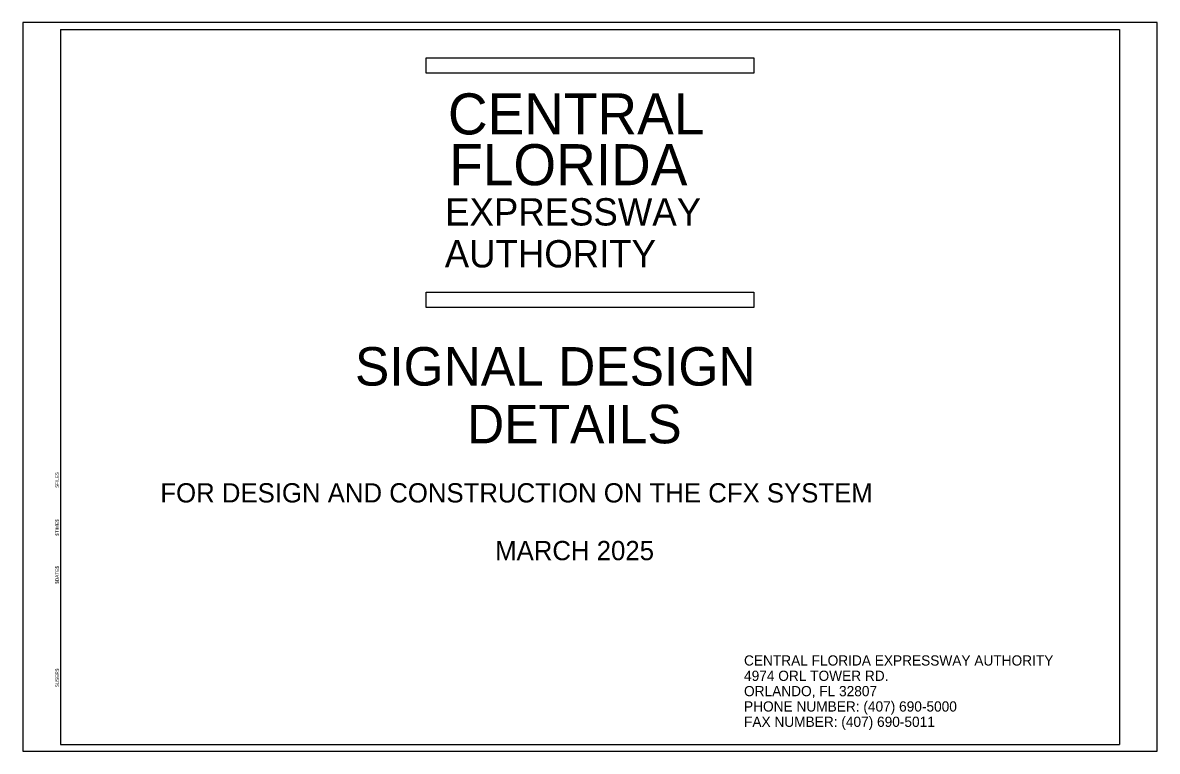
# Model space of a CAD drawing. Extents: x 1888.7 to 1905.2, y -90 to -79.4.
import ezdxf

# ---------------------------------------------------------------- set-up
doc = ezdxf.new("R2010")
doc.units = 0
for name, color, linetype in [('PlotBorder_dp', 7, 'Continuous'), ('SheetBorder_dp', 7, 'Continuous'), ('SignPanel', 7, 'Continuous'), ('TextLabel', 7, 'Continuous'), ('TextMisc', 7, 'Continuous'), ('TextStructures', 7, 'Continuous')]:
    doc.layers.add(name, color=color, linetype=linetype)

msp = doc.modelspace()

# ---------------------------------------------------------------- linework, layer by layer
at = {"layer": 'PlotBorder_dp'}
msp.add_lwpolyline([(1888.731, -90), (1905.231, -90), (1905.231, -79.4), (1888.731, -79.4)], close=True, dxfattribs=at)
at = {"layer": 'SheetBorder_dp'}
for p, q in [((1889.281, -79.5), (1889.281, -89.9)), ((1889.281, -79.5), (1904.681, -79.5)), ((1904.681, -79.5), (1904.681, -89.9)), ((1889.281, -89.9), (1904.681, -89.9))]:
    msp.add_line(p, q, dxfattribs=at)
at = {"layer": 'SignPanel'}
for points in [[(1894.598, -79.914), (1899.364, -79.914), (1899.364, -80.137), (1894.598, -80.137)], [(1894.598, -83.32), (1899.364, -83.32), (1899.364, -83.543), (1894.598, -83.543)]]:
    msp.add_lwpolyline(points, close=True, dxfattribs=at)

# ---------------------------------------------------------------- texts
for s, height, p in [('CENTRAL', 0.5974, (1894.915, -81.026)), ('FLORIDA', 0.5974, (1894.935, -81.765)), ('EXPRESSWAY', 0.3976, (1894.874, -82.351)), ('AUTHORITY', 0.3976, (1894.869, -82.961))]:
    msp.add_text(s, height=height, dxfattribs=at).set_placement(p)
at = {"layer": 'TextLabel'}
for s, p in [('SIGNAL DESIGN', (1893.563, -84.68)), ('DETAILS', (1895.193, -85.52))]:
    msp.add_text(s, height=0.56, dxfattribs=at).set_placement(p)
at = {"layer": 'TextMisc'}
for s, p in [('$FILE$', (1889.256, -86.165)), ('$TIME$', (1889.256, -86.865)), ('$DATE$', (1889.256, -87.565)), ('$USER$', (1889.256, -89.065))]:
    msp.add_text(s, height=0.05, rotation=90, dxfattribs=at).set_placement(p)
at = {"layer": 'TextStructures'}
for s, height, p in [('FOR DESIGN AND CONSTRUCTION ON THE CFX SYSTEM', 0.28, (1890.733, -86.38)), ('MARCH 2025', 0.28, (1895.602, -87.22)), ('CENTRAL FLORIDA EXPRESSWAY AUTHORITY', 0.14875, (1899.221, -88.753)), ('4974 ORL TOWER RD.', 0.14875, (1899.221, -88.976)), ('ORLANDO, FL 32807', 0.14875, (1899.221, -89.199)), ('PHONE NUMBER: (407) 690-5000', 0.14875, (1899.221, -89.422)), ('FAX NUMBER: (407) 690-5011', 0.14875, (1899.221, -89.645))]:
    msp.add_text(s, height=height, dxfattribs=at).set_placement(p)

doc.saveas('drawing.dxf')
